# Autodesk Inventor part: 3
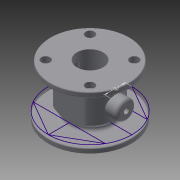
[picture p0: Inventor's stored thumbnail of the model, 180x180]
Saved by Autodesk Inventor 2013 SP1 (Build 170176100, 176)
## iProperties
Created: 2013-05
Part Number: 3
Material: Steel, Mild
Document SubType Name: Modeling
Designer: 50384
Density: 1 g/cm^3
Author: 50384
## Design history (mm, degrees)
sketch "Sketch1"
  geometry: C1 r 40 at (0, 0); 1 further point
  constraints: 1 centre point, 1 coincident
  dimensions: "d0" = 80 diameter of C1
extrude "Extrusion1" new body sketch "Sketch1" distance "d1" = 5; taper "d2" = 0 deg
sketch "Sketch2"
  geometry: C1 r 40 at (0, 0) reference; C2 r 20 at (0, 0)
  constraints: 1 centre point, 1 coincident
  dimensions: "d3" = 40 diameter of C2
extrude "Extrusion2" join sketch "Sketch2" distance "d4" = 40; taper "d5" = 0 deg
sketch "Sketch3"
  geometry: C1 r 20 at (0, 0) reference; C2 r 40 at (0, 0) reference
extrude "Extrusion3" join sketch "Sketch3" distance "d6" = 5; taper "d7" = 0 deg
fillet "Fillet1" dims "d9" = 3
workplane "Work Plane2"
sketch "Sketch4"
  geometry: C1 r 25 at (0, 0); 1 further point
  constraints: 1 centre point, 1 coincident
  dimensions: "d11" = 50 diameter of C1
extrude "Extrusion4" join sketch "Sketch4" distance "d12" = 34; taper "d13" = 0 deg
fillet "Fillet2" dims "d14" = 3
sketch "Sketch5"
  geometry: L1 (42, -25)-(42, 25) reference; L2 (8, 25)-(8, -25) reference; L3 (5, -40)-(5, 40) reference; L4 (0, 40)-(0, -40) reference; L5 (50, -40)-(50, 40) reference; L6 (45, 40)-(45, -40) reference; L7 (0, 0)-(50, 0); C1 r 9 at (25, 0)
  constraints: 2 end point, 2 midpoint, 1 centre point
  dimensions: "d15" = 18 diameter of C1
extrude "Extrusion5" join sketch "Sketch5" stored distance "d16" = 70; taper "d17" = 0 deg
sketch "Sketch6"
  geometry: C1 r 9 at (0, 0) reference; C2 r 2.5 at (0, 0); 1 further point
  constraints: 1 centre point, 1 coincident
  dimensions: "d18" = 5 diameter of C2
extrude "Extrusion6" cut sketch "Sketch6" distance "d19" = 70; taper "d20" = 0 deg
fillet "Fillet4" dims "d22" = 3
workplane "Work Plane4"
sketch "Sketch7"
  geometry: L1 (0, 40)-(0, 20); L2 (0, 20)-(34.641, 20); L3 (0, 20)-(-34.641, 20); L4 (0, 40)-(-34.641, 20); L5 (-40, 0)-(40, 0); L6 (0, -40)-(0, -20); L7 (0, -20)-(34.641, -20); L8 (0, -20)-(-34.641, -20); L9 (0, -40)-(-34.641, -20); L10 (0, 40)-(34.641, 20); L11 (34.641, -20)-(0, -40); A1 r 40 centre (0, 0) between (0, 40) and (34.641, 20) reference; A2 r 40 centre (0, 0) between (0, -40) and (34.641, -20); 1 further point
  constraints: 22 end point, 9 point on circle, 4 symmetric about line, 3 parallel, 1 centre point, 1 collinear, 1 perpendicular, 1 point on line, 1 vertical, 1 other
  dimensions: "d26" = 20 distance of L1.start L1.end
  node "Projected Loop5"
extrude "Extrusion7" cut sketch "Sketch7" stored distance "d27" = 70; taper "d28" = 0 deg
sketch "Sketch8"
  geometry: C1 r 40 at (0, 0) reference; C2 r 12.5 at (0, 0)
  constraints: 1 centre point, 1 coincident
  dimensions: "d30" = 25 diameter of C2
extrude "Extrusion8" cut sketch "Sketch8" distance "d31" = 45; taper "d32" = 0 deg
sketch "Sketch9"
  geometry: C1 r 12.5 at (0, 0) reference; C2 r 4 at (0, 0)
  constraints: 1 centre point, 1 coincident
  dimensions: "d33" = 8 diameter of C2
extrude "Extrusion9" cut sketch "Sketch9" distance "d34" = 45; taper "d35" = 0 deg
sketch "Sketch10"
  geometry: L1 (0, 0)-(38.1, 0); C1 r 40 at (0, 0) reference; C2 r 38 at (0, 0); C3 r 4.25 at (21.213, -21.213); C4 r 4.25 at (21.213, 21.213); C5 r 4.25 at (-21.213, 21.213); C6 r 4.25 at (-21.213, -21.213)
  constraints: 5 centre point, 2 end point, 1 horizontal
  dimensions: "d37" = 76 diameter of C2; "d40" = 8.5 diameter of C3
extrude "Extrusion10" cut sketch "Sketch10" distance "d44" = 10; taper "d45" = 0 deg
sketch "Sketch11"
  geometry: C1 r 2.5 at (0, 0) reference; C2 r 6 at (0, 0) reference; C3 r 6 at (0, 0); 1 further point
  constraints: 1 centre point, 1 coincident
  dimensions: "d46" = 12 diameter of C3
extrude "Extrusion11" cut sketch "Sketch11" distance "d47" = 25; taper "d48" = 0 deg
fillet "Fillet6" dims "d49" = 1
workplane "Work Plane3"
sketch "Sketch12"
  geometry: C1 r 12.5 at (0, 0) reference; C2 r 2.5 at (-12.5, 0); 1 further point
  constraints: 1 centre point
  dimensions: "d51" = 5 diameter of C2
extrude "Extrusion12" cut sketch "Sketch12" distance "d52" = 34; taper "d53" = 0 deg
chamfer "Chamfer2" distance "d54" = 5; stored, may be unused: second distance "d55" = 3.175, angle "d56" = 45 deg
extrude "Extrusion13" cut sketch "Sketch7" distance "d57" = 34; taper "d58" = 0 deg
fillet "Fillet7" dims "d59" = 5
body "Solid1"
node "Projected Loop1"
node "Projected Loop3"
node "Projected Loop4"
